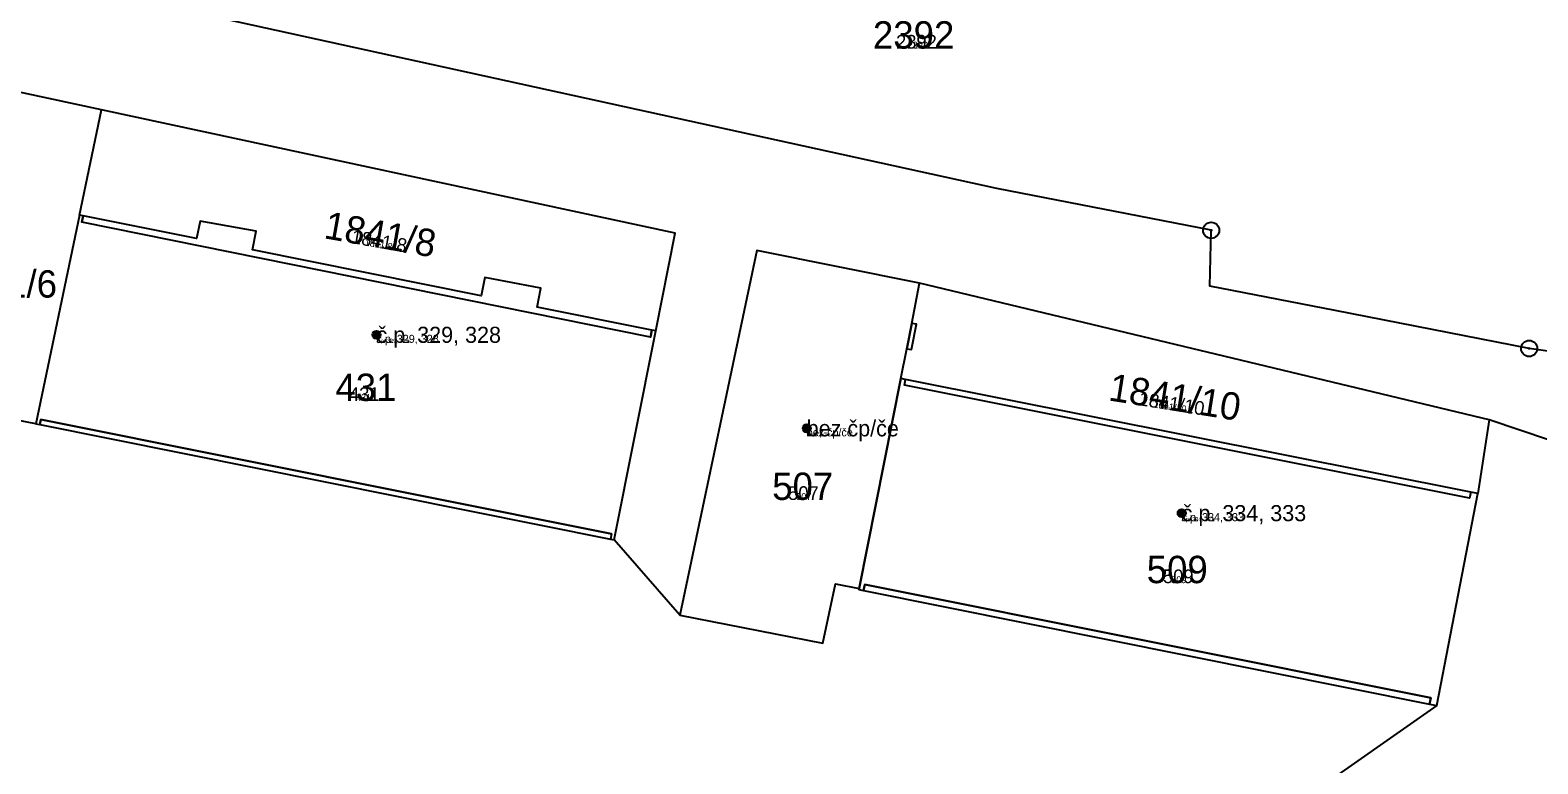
# Model space of a CAD drawing. Extents: x -744652 to -739090, y -980828 to -975855.
# Drawn here: x -742712.9 to -742619.3, y -978532.1 to -978486.5 of the extents above; entities that cross this region are included whole.
import ezdxf

# ---------------------------------------------------------------- set-up
doc = ezdxf.new("R2010")
doc.units = 0
for name, color, linetype in [('KAT_02_hranice parcel', 7, 'Continuous'), ('KAT_03_1000_st čísla parcelní', 7, 'Continuous'), ('KAT_03_1000_čísla parcelní', 7, 'Continuous'), ('KAT_03_1000_čísla popisná', 7, 'Continuous'), ('KAT_03_100_st čísla parcelní', 7, 'Continuous'), ('KAT_03_100_čísla parcelní', 7, 'Continuous'), ('KAT_03_100_čísla popisná', 7, 'Continuous'), ('KAT_03_250_st čísla parcelní', 7, 'Continuous'), ('KAT_03_250_čísla parcelní', 7, 'Continuous'), ('KAT_03_250_čísla popisná', 7, 'Continuous'), ('KAT_03_500_st čísla parcelní', 7, 'Continuous'), ('KAT_03_500_čísla parcelní', 7, 'Continuous'), ('KAT_03_500_čísla popisná', 7, 'Continuous'), ('KAT_04_vnitřní kresba', 7, 'Continuous'), ('KAT_07_1000_značky budov', 7, 'Continuous'), ('KAT_07_100_značky budov', 7, 'Continuous'), ('KAT_07_500_značky budov', 7, 'Continuous'), ('KAT_11_značky bodu BP', 7, 'Continuous'), ('KAT_14_plocha_budovy', 7, 'Continuous')]:
    doc.layers.add(name, color=color, linetype=linetype)

msp = doc.modelspace()

# ---------------------------------------------------------------- linework, layer by layer
at = {"layer": 'KAT_02_hranice parcel'}
for p, q in [((-742708.48, -978491.48), (-742716.28, -978489.8)), ((-742709.85, -978498.01), (-742708.48, -978491.48)), ((-742709.85, -978498.01), (-742712.56, -978510.98)), ((-742622.3, -978510.73), (-742657.69, -978502.24)), ((-742676.64, -978518.19), (-742674.07, -978505.21)), ((-742661.44, -978521.21), (-742658.84, -978508.17)), ((-742712.56, -978510.98), (-742720.39, -978509.46)), ((-742622.3, -978510.73), (-742623, -978515.31)), ((-742625.56, -978528.48), (-742623, -978515.31)), ((-742672.56, -978522.87), (-742676.64, -978518.19)), ((-742625.56, -978528.48), (-742633.57, -978534.1))]:
    msp.add_line(p, q, dxfattribs=at)
for points in [[(-742598.56, -978509.34), (-742604.99, -978508.42), (-742619.82, -978506.3), (-742631.87, -978503.95), (-742639.66, -978502.43), (-742639.57, -978498.96), (-742652.89, -978496.37), (-742719.91, -978481.64)], [(-742674.07, -978505.21), (-742672.87, -978499.13), (-742708.48, -978491.48)], [(-742674.07, -978505.21), (-742674.31, -978505.16), (-742681.44, -978503.73), (-742681.2, -978502.56), (-742684.68, -978501.9), (-742684.91, -978503.03), (-742699.12, -978500.17), (-742698.89, -978499.02), (-742702.36, -978498.4), (-742702.58, -978499.47), (-742709.63, -978498.05), (-742709.85, -978498.01)], [(-742657.69, -978502.24), (-742667.79, -978500.22), (-742672.56, -978522.87)], [(-742658.84, -978508.17), (-742658.48, -978506.32), (-742658.19, -978506.37), (-742657.88, -978504.8), (-742658.17, -978504.74), (-742657.69, -978502.24)], [(-742623, -978515.31), (-742623.44, -978515.22), (-742658.55, -978508.23), (-742658.84, -978508.17)], [(-742712.56, -978510.98), (-742712.31, -978511.03), (-742676.88, -978518.14), (-742676.64, -978518.19)], [(-742520.5, -978587.81), (-742525.48, -978582.81), (-742528, -978581.12), (-742545.21, -978576.36), (-742546.31, -978580.73), (-742562.58, -978576.21), (-742561.25, -978571.75), (-742586.77, -978562.57), (-742590.71, -978559.78), (-742594.6, -978552.66), (-742597.04, -978540.63), (-742597.4, -978531.66), (-742598.83, -978526.88), (-742601.73, -978521.76), (-742606.95, -978517.23), (-742612.97, -978513.89), (-742622.3, -978510.73)], [(-742672.56, -978522.87), (-742663.68, -978524.6), (-742662.91, -978520.92), (-742661.44, -978521.21)], [(-742661.44, -978521.21), (-742661.45, -978521.28), (-742661.17, -978521.34), (-742626, -978528.39), (-742625.56, -978528.48)]]:
    msp.add_lwpolyline(points, dxfattribs=at)
at = {"layer": 'KAT_03_1000_čísla popisná'}
for centre in [(-742691.41, -978505.45), (-742691.41, -978505.45), (-742664.69, -978511.26), (-742664.69, -978511.26), (-742641.4, -978516.53), (-742641.4, -978516.53)]:
    msp.add_circle(centre, 0.25, dxfattribs=at)
at = {"layer": 'KAT_03_100_čísla popisná'}
for centre in [(-742691.41, -978505.45), (-742691.41, -978505.45), (-742664.69, -978511.26), (-742664.69, -978511.26), (-742641.4, -978516.53), (-742641.4, -978516.53)]:
    msp.add_circle(centre, 0.025, dxfattribs=at)
at = {"layer": 'KAT_03_250_čísla popisná'}
for centre in [(-742691.41, -978505.45), (-742691.41, -978505.45), (-742664.69, -978511.26), (-742664.69, -978511.26), (-742641.4, -978516.53), (-742641.4, -978516.53)]:
    msp.add_circle(centre, 0.0625, dxfattribs=at)
at = {"layer": 'KAT_03_500_čísla popisná'}
for centre in [(-742691.41, -978505.45), (-742691.41, -978505.45), (-742664.69, -978511.26), (-742664.69, -978511.26), (-742641.4, -978516.53), (-742641.4, -978516.53)]:
    msp.add_circle(centre, 0.125, dxfattribs=at)
at = {"layer": 'KAT_04_vnitřní kresba'}
for p, q in [((-742709.63, -978498.05), (-742709.72, -978498.45)), ((-742674.39, -978505.59), (-742709.72, -978498.45)), ((-742674.39, -978505.59), (-742674.31, -978505.16)), ((-742658.17, -978504.74), (-742658.48, -978506.32)), ((-742658.62, -978508.58), (-742658.55, -978508.23)), ((-742623.52, -978515.59), (-742658.62, -978508.58)), ((-742712.25, -978510.71), (-742712.31, -978511.03)), ((-742676.81, -978517.81), (-742712.25, -978510.71)), ((-742623.44, -978515.22), (-742623.52, -978515.59)), ((-742676.81, -978517.81), (-742676.88, -978518.14)), ((-742661.09, -978520.96), (-742661.17, -978521.34)), ((-742625.92, -978528), (-742661.09, -978520.96)), ((-742626, -978528.39), (-742625.92, -978528))]:
    msp.add_line(p, q, dxfattribs=at)
at = {"layer": 'KAT_07_1000_značky budov'}
for centre in [(-742691.417, -978505.449), (-742664.697, -978511.259), (-742641.407, -978516.529)]:
    msp.add_circle(centre, 0.175, dxfattribs=at)
at = {"layer": 'KAT_07_100_značky budov'}
for centre in [(-742691.411, -978505.45), (-742664.691, -978511.26), (-742641.401, -978516.53)]:
    msp.add_circle(centre, 0.0175, dxfattribs=at)
at = {"layer": 'KAT_07_500_značky budov'}
for centre, radius in [((-742691.413, -978505.45), 0.0875), ((-742691.412, -978505.45), 0.0438), ((-742664.693, -978511.26), 0.0875), ((-742664.692, -978511.26), 0.0438), ((-742641.403, -978516.53), 0.0875), ((-742641.402, -978516.53), 0.0438)]:
    msp.add_circle(centre, radius, dxfattribs=at)
at = {"layer": 'KAT_11_značky bodu BP'}
for centre, radius in [((-742639.57, -978498.96), 0.5), ((-742639.57, -978498.96), 0.0303), ((-742619.82, -978506.3), 0.5), ((-742619.82, -978506.3), 0.0303)]:
    msp.add_circle(centre, radius, dxfattribs=at)
at = {"layer": 'KAT_14_plocha_budovy'}
for points in [[(-742712.56, -978510.98), (-742712.31, -978511.03), (-742712.25, -978510.71), (-742676.81, -978517.81), (-742676.88, -978518.14), (-742676.64, -978518.19), (-742674.07, -978505.21), (-742674.31, -978505.16), (-742674.39, -978505.59), (-742709.72, -978498.45), (-742709.63, -978498.05), (-742709.85, -978498.01)], [(-742661.44, -978521.21), (-742658.84, -978508.17), (-742658.48, -978506.32), (-742658.17, -978504.74), (-742657.69, -978502.24), (-742667.79, -978500.22), (-742672.56, -978522.87), (-742663.68, -978524.6), (-742662.91, -978520.92)], [(-742661.44, -978521.21), (-742661.45, -978521.28), (-742661.17, -978521.34), (-742661.09, -978520.96), (-742625.92, -978528), (-742626, -978528.39), (-742625.56, -978528.48), (-742623, -978515.31), (-742623.44, -978515.22), (-742623.52, -978515.59), (-742658.62, -978508.58), (-742658.55, -978508.23), (-742658.84, -978508.17)]]:
    msp.add_lwpolyline(points, close=True, dxfattribs=at)

# ---------------------------------------------------------------- texts
at = {"layer": 'KAT_03_1000_st čísla parcelní'}
for s, p in [('431', (-742693.964, -978509.56)), ('507', (-742666.834, -978515.71)), ('509', (-742643.574, -978520.88))]:
    msp.add_text(s, height=1.7, dxfattribs=at).set_placement(p)
at = {"layer": 'KAT_03_1000_čísla parcelní'}
for s, p in [('2392', (-742660.577, -978487.67)), ('1841/6', (-742718.205, -978503.14))]:
    msp.add_text(s, height=1.7, dxfattribs=at).set_placement(p)
for s, rotation, p in [('1841/8', 350, (-742694.733, -978499.443)), ('1841/10', 351, (-742646.003, -978509.519))]:
    msp.add_text(s, height=1.7, rotation=rotation, dxfattribs=at).set_placement(p)
at = {"layer": 'KAT_03_1000_čísla popisná'}
for s, height, p in [('č.p. 329, 328', 1, (-742691.41, -978505.95)), ('431', 0.017, (-742692.288, -978509.56)), ('bez čp/če', 1, (-742664.69, -978511.76)), ('507', 0.017, (-742664.866, -978515.71)), ('č.p. 334, 333', 1, (-742641.4, -978517.03)), ('509', 0.017, (-742641.567, -978520.88))]:
    msp.add_text(s, height=height, dxfattribs=at).set_placement(p)
at = {"layer": 'KAT_03_100_st čísla parcelní'}
for s, p in [('431', (-742692.44, -978509.56)), ('507', (-742665.045, -978515.71)), ('509', (-742641.749, -978520.88))]:
    msp.add_text(s, height=0.17, dxfattribs=at).set_placement(p)
at = {"layer": 'KAT_03_100_čísla parcelní'}
msp.add_text('2392', height=0.17, dxfattribs=at).set_placement((-742657.987, -978487.67))
for s, rotation, p in [('1841/8', 350, (-742691.655, -978499.986)), ('1841/10', 351, (-742642.606, -978510.057))]:
    msp.add_text(s, height=0.17, rotation=rotation, dxfattribs=at).set_placement(p)
at = {"layer": 'KAT_03_100_čísla popisná'}
for s, height, p in [('č.p. 329, 328', 0.1, (-742691.41, -978505.95)), ('431', 0.0017, (-742692.273, -978509.56)), ('bez čp/če', 0.1, (-742664.69, -978511.76)), ('507', 0.0017, (-742664.848, -978515.71)), ('č.p. 334, 333', 0.1, (-742641.4, -978517.03)), ('509', 0.0017, (-742641.548, -978520.88))]:
    msp.add_text(s, height=height, dxfattribs=at).set_placement(p)
at = {"layer": 'KAT_03_250_st čísla parcelní'}
for s, p in [('431', (-742692.694, -978509.56)), ('507', (-742665.343, -978515.71)), ('509', (-742642.053, -978520.88))]:
    msp.add_text(s, height=0.425, dxfattribs=at).set_placement(p)
at = {"layer": 'KAT_03_250_čísla parcelní'}
msp.add_text('2392', height=0.425, dxfattribs=at).set_placement((-742658.419, -978487.67))
for s, rotation, p in [('1841/8', 350, (-742692.168, -978499.895)), ('1841/10', 351, (-742643.172, -978509.967))]:
    msp.add_text(s, height=0.425, rotation=rotation, dxfattribs=at).set_placement(p)
at = {"layer": 'KAT_03_250_čísla popisná'}
for s, height, p in [('č.p. 329, 328', 0.25, (-742691.41, -978505.95)), ('431', 0.00425, (-742692.275, -978509.56)), ('bez čp/če', 0.25, (-742664.69, -978511.76)), ('507', 0.00425, (-742664.851, -978515.71)), ('č.p. 334, 333', 0.25, (-742641.4, -978517.03)), ('509', 0.00425, (-742641.551, -978520.88))]:
    msp.add_text(s, height=height, dxfattribs=at).set_placement(p)
at = {"layer": 'KAT_03_500_st čísla parcelní'}
for s, p in [('431', (-742693.117, -978509.56)), ('507', (-742665.84, -978515.71)), ('509', (-742642.56, -978520.88))]:
    msp.add_text(s, height=0.85, dxfattribs=at).set_placement(p)
at = {"layer": 'KAT_03_500_čísla parcelní'}
msp.add_text('2392', height=0.85, dxfattribs=at).set_placement((-742659.138, -978487.67))
for s, rotation, p in [('1841/8', 350, (-742693.023, -978499.745)), ('1841/10', 351, (-742644.116, -978509.818))]:
    msp.add_text(s, height=0.85, rotation=rotation, dxfattribs=at).set_placement(p)
at = {"layer": 'KAT_03_500_čísla popisná'}
for s, height, p in [('č.p. 329, 328', 0.5, (-742691.41, -978505.95)), ('431', 0.0085, (-742692.279, -978509.56)), ('bez čp/če', 0.5, (-742664.69, -978511.76)), ('507', 0.0085, (-742664.856, -978515.71)), ('č.p. 334, 333', 0.5, (-742641.4, -978517.03)), ('509', 0.0085, (-742641.556, -978520.88))]:
    msp.add_text(s, height=height, dxfattribs=at).set_placement(p)

doc.saveas('drawing.dxf')
